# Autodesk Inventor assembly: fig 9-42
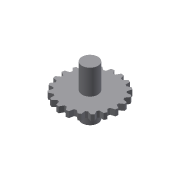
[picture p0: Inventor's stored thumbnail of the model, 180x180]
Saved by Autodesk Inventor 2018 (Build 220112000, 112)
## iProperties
Created: 2013-07
Part Number: fig 9-42
Document SubType Name: Assembly
Designer: CADCIM
Author: CADCIM
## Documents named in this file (3)
- E:\_Deepak\Inventor\Autodesk Inventor_2017_Project\Resources\Inventor_2018_Part\c09_Inv_2018\c09_inv_2018_prt\fig 9-42.iam
- E:\_Deepak\Inventor\Autodesk Inventor_2017_Project\Resources\Inventor_2018_Part\c09_Inv_2018\c09_inv_2018_prt\13.ipt
- E:\_Deepak\Inventor\Autodesk Inventor_2017_Project\Resources\Inventor_2018_Part\c09_Inv_2018\c09_inv_2018_prt\14.ipt
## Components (2 placed, 2 different names)
1. 13:1 — Rotational:1
2. 14:1 — Rotational:1
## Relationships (1: RevoluteJoint 1)
- Rotational:1 [RevoluteJoint]: 13:1 ↔ 14:1
